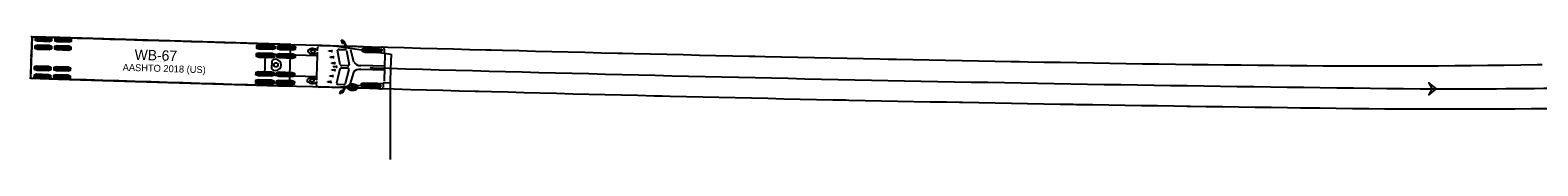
# Model space of a CAD drawing. Extents: x 973688 to 979179, y 703586 to 707602.
# Drawn here: x 976765.6 to 977073.4, y 704010.6 to 704035.6 of the extents above; entities that cross this region are included whole.
import ezdxf

# ---------------------------------------------------------------- set-up
doc = ezdxf.new("R2010")
doc.units = 0
doc.layers.add('SB Left', color=7, linetype='Continuous')
doc.layers.add('SB Right', color=7, linetype='Continuous')

msp = doc.modelspace()

# ---------------------------------------------------------------- linework, layer by layer
at = {"layer": 'SB Left'}
msp.add_line((976839.13, 704026.21), (976839.13, 704010.57), dxfattribs=at)
at = {"layer": 'SB Right'}
for p, q in [((976765.76, 704027.11), (976766.02, 704035.61)), ((976765.95, 704035.57), (976765.84, 704031.93)), ((976766.02, 704035.61), (976765.95, 704035.61)), ((976765.95, 704035.61), (976765.95, 704035.59)), ((976765.95, 704035.57), (976765.95, 704035.57)), ((976771.69, 704035.44), (976766.02, 704035.61)), ((976770.01, 704034.8), (976766.71, 704034.9)), ((976770.02, 704035.26), (976766.72, 704035.36)), ((976770.01, 704035.03), (976766.72, 704035.13)), ((976774.01, 704034.91), (976770.71, 704035.01)), ((976774.01, 704034.68), (976770.71, 704034.78)), ((976774.02, 704035.14), (976770.72, 704035.24)), ((976818.86, 704034.01), (976771.69, 704035.44)), ((976818.73, 704029.76), (976818.86, 704034.01)), ((976829.41, 704034.25), (976829.18, 704034.98)), ((976829.18, 704034.98), (976829.18, 704034.98)), ((976829.18, 704034.98), (976829.3, 704034.97)), ((976829.3, 704034.97), (976829.3, 704034.97)), ((976829.3, 704034.97), (976829.53, 704034.65)), ((976829.52, 704034.25), (976829.41, 704034.25)), ((976829.54, 704034.59), (976829.52, 704034.25)), ((976829.53, 704034.65), (976829.53, 704034.64)), ((976829.55, 704034.62), (976829.53, 704034.64)), ((976829.53, 704034.64), (976829.62, 704034.64)), ((976829.54, 704034.59), (976829.55, 704034.62)), ((976829.62, 704034.59), (976829.54, 704034.59)), ((976829.54, 704034.59), (976829.54, 704034.59)), ((976829.63, 704034.59), (976829.62, 704034.59)), ((976829.62, 704034.59), (976829.62, 704034.59)), ((976829.66, 704034.58), (976829.63, 704034.59)), ((976830.04, 704033.67), (976829.66, 704034.58)), ((976829.66, 704034.58), (976829.66, 704034.58)), ((976829.75, 704034.59), (976830.14, 704033.68)), ((976765.8, 704030.8), (976765.69, 704027.16)), ((976765.74, 704031.1), (976765.74, 704030.84)), ((976765.74, 704030.84), (976765.74, 704030.84)), ((976765.74, 704030.84), (976765.81, 704030.83)), ((976765.77, 704031.9), (976765.76, 704031.63)), ((976765.84, 704031.9), (976765.77, 704031.9)), ((976765.77, 704031.9), (976765.77, 704031.9)), ((976765.81, 704030.83), (976765.8, 704030.8)), ((976765.83, 704031.62), (976765.81, 704031.1)), ((976765.81, 704030.83), (976765.81, 704031.1)), ((976765.82, 704031.36), (976765.89, 704031.36)), ((976765.83, 704031.63), (976765.84, 704031.9)), ((976765.84, 704031.93), (976765.84, 704031.9)), ((976769.96, 704033.15), (976766.66, 704033.25)), ((976769.97, 704033.61), (976766.67, 704033.71)), ((976769.96, 704033.38), (976766.67, 704033.48)), ((976773.96, 704033.26), (976770.66, 704033.36)), ((976773.96, 704033.03), (976770.66, 704033.13)), ((976773.97, 704033.49), (976770.67, 704033.59)), ((976815.52, 704031.75), (976811.85, 704031.86)), ((976815.51, 704031.52), (976811.85, 704031.63)), ((976815.53, 704031.98), (976811.86, 704032.09)), ((976815.57, 704033.4), (976811.9, 704033.51)), ((976815.56, 704033.17), (976811.9, 704033.28)), ((976815.58, 704033.63), (976811.91, 704033.74)), ((976813.63, 704029.92), (976813.69, 704032.08)), ((976813.69, 704032.08), (976824.05, 704031.77)), ((976819.72, 704031.62), (976816.05, 704031.73)), ((976819.71, 704031.39), (976816.05, 704031.51)), ((976819.72, 704031.85), (976816.06, 704031.96)), ((976819.77, 704033.27), (976816.1, 704033.38)), ((976819.76, 704033.04), (976816.1, 704033.15)), ((976819.77, 704033.5), (976816.11, 704033.61)), ((976824.05, 704031.77), (976824.29, 704031.76)), ((976824.16, 704027.43), (976824.29, 704031.76)), ((976824.29, 704031.76), (976824.31, 704032.44)), ((976824.32, 704032.73), (976824.35, 704033.57)), ((976824.87, 704033.83), (976830.04, 704033.67)), ((976826.59, 704032.71), (976827.14, 704032.73)), ((976826.59, 704032.62), (976826.59, 704032.71)), ((976827.14, 704032.56), (976826.59, 704032.62)), ((976826.94, 704031.48), (976827.52, 704031.5)), ((976826.94, 704031.39), (976826.94, 704031.48)), ((976827.51, 704031.34), (976826.94, 704031.39)), ((976827.79, 704033.74), (976837.89, 704032.27)), ((976828.9, 704029.88), (976828.34, 704032.83)), ((976828.72, 704033.02), (976829.85, 704032.98)), ((976830.04, 704033.67), (976830.14, 704033.67)), ((976830.14, 704033.68), (976830.15, 704033.67)), ((976830.15, 704033.67), (976837.4, 704033.45)), ((976830.22, 704032.81), (976830.77, 704029.85)), ((976831.68, 704030.44), (976831.12, 704032.92)), ((976837.16, 704032.75), (976833.49, 704032.86)), ((976837.15, 704032.52), (976833.49, 704032.63)), ((976837.17, 704032.97), (976833.5, 704033.09)), ((976837.06, 704032.63), (976837.07, 704033.05)), ((976837.42, 704032.62), (976837.06, 704032.63)), ((976837.07, 704033.05), (976837.43, 704033.04)), ((976837.43, 704033.04), (976837.42, 704032.62)), ((976837.91, 704033.14), (976837.89, 704032.28)), ((976837.89, 704032.28), (976837.89, 704032.27)), ((976837.89, 704032.27), (976839.31, 704032.06)), ((976837.94, 704026.54), (976838.11, 704032.1)), ((976839.3, 704032), (976839.22, 704029.14)), ((976839.31, 704032.06), (976839.3, 704032)), ((976769.79, 704027.68), (976766.49, 704027.78)), ((976769.83, 704028.87), (976766.53, 704028.97)), ((976769.84, 704029.33), (976766.54, 704029.43)), ((976769.83, 704029.1), (976766.54, 704029.2)), ((976773.83, 704028.98), (976770.53, 704029.08)), ((976773.83, 704028.75), (976770.53, 704028.85)), ((976773.84, 704029.21), (976770.54, 704029.31)), ((976815.4, 704027.74), (976811.73, 704027.85)), ((976815.4, 704027.97), (976811.74, 704028.08)), ((976815.41, 704028.2), (976811.75, 704028.31)), ((976813.56, 704027.75), (976813.63, 704029.92)), ((976823.92, 704027.44), (976813.56, 704027.75)), ((976814.94, 704030.68), (976814.9, 704029.06)), ((976819.6, 704027.61), (976815.93, 704027.72)), ((976819.61, 704028.07), (976815.94, 704028.18)), ((976819.6, 704027.84), (976815.94, 704027.95)), ((976818.6, 704025.51), (976818.73, 704029.76)), ((976827.19, 704028.75), (976827.2, 704028.84)), ((976827.74, 704028.7), (976827.19, 704028.75)), ((976827.2, 704028.84), (976827.75, 704028.86)), ((976827.24, 704030.25), (976827.79, 704030.28)), ((976827.24, 704030.16), (976827.24, 704030.25)), ((976827.78, 704030.11), (976827.24, 704030.16)), ((976827.52, 704029.45), (976827.53, 704029.54)), ((976828.07, 704029.39), (976827.52, 704029.45)), ((976827.53, 704029.54), (976828.08, 704029.56)), ((976828.87, 704029.03), (976828.14, 704026.11)), ((976830.38, 704029.15), (976829.25, 704029.18)), ((976830.39, 704029.67), (976829.26, 704029.7)), ((976830.01, 704026.02), (976830.74, 704028.94)), ((976831.62, 704028.3), (976830.91, 704025.84)), ((976838, 704028.76), (976833.11, 704028.91)), ((976838.03, 704029.59), (976833.14, 704029.74)), ((976839.22, 704029.14), (976839.13, 704026.28)), ((976765.69, 704027.16), (976765.69, 704027.16)), ((976765.69, 704027.14), (976765.69, 704027.12)), ((976765.69, 704027.12), (976765.76, 704027.12)), ((976765.76, 704027.12), (976771.43, 704026.94)), ((976769.78, 704027.22), (976766.48, 704027.32)), ((976769.78, 704027.45), (976766.49, 704027.55)), ((976773.78, 704027.33), (976770.48, 704027.43)), ((976773.78, 704027.1), (976770.48, 704027.2)), ((976773.79, 704027.56), (976770.49, 704027.66)), ((976771.43, 704026.94), (976818.6, 704025.51)), ((976815.35, 704026.09), (976811.68, 704026.2)), ((976815.35, 704026.32), (976811.69, 704026.43)), ((976815.36, 704026.55), (976811.7, 704026.66)), ((976819.55, 704025.96), (976815.88, 704026.07)), ((976819.56, 704026.42), (976815.89, 704026.53)), ((976819.55, 704026.19), (976815.89, 704026.3)), ((976824.16, 704027.43), (976823.92, 704027.44)), ((976824.1, 704025.62), (976824.13, 704026.46)), ((976824.14, 704026.74), (976824.16, 704027.43)), ((976829.78, 704025.17), (976824.61, 704025.33)), ((976826.4, 704026.43), (976826.95, 704026.45)), ((976826.4, 704026.34), (976826.4, 704026.43)), ((976826.95, 704026.28), (976826.4, 704026.34)), ((976826.82, 704027.55), (976826.83, 704027.64)), ((976827.37, 704027.49), (976826.82, 704027.55)), ((976826.83, 704027.64), (976827.38, 704027.66)), ((976827.53, 704025.24), (976830.33, 704025.48)), ((976828.5, 704025.9), (976829.63, 704025.87)), ((976828.84, 704023.92), (976829.12, 704024.63)), ((976829.12, 704024.63), (976829.22, 704024.63)), ((976829.35, 704024.29), (976829.78, 704025.17)), ((976829.88, 704025.16), (976829.44, 704024.27)), ((976829.78, 704025.17), (976829.88, 704025.17)), ((976829.89, 704025.17), (976829.88, 704025.16)), ((976830.32, 704025.16), (976829.89, 704025.17)), ((976832.29, 704025.64), (976837.7, 704026.09)), ((976837.14, 704024.95), (976832.5, 704025.09)), ((976836.94, 704025.44), (976833.27, 704025.55)), ((976836.94, 704025.66), (976833.28, 704025.78)), ((976836.95, 704025.89), (976833.29, 704026.01)), ((976836.85, 704025.78), (976836.84, 704025.37)), ((976836.84, 704025.37), (976837.2, 704025.36)), ((976837.21, 704025.77), (976836.85, 704025.78)), ((976837.2, 704025.36), (976837.21, 704025.77)), ((976837.7, 704026.09), (976837.67, 704025.23)), ((976839.13, 704026.21), (976837.7, 704026.09)), ((976837.7, 704026.09), (976837.7, 704026.09)), ((976839.13, 704026.28), (976839.13, 704026.21)), ((976828.96, 704023.92), (976828.84, 704023.92)), ((976828.84, 704023.92), (976828.84, 704023.92)), ((976829.21, 704024.23), (976828.96, 704023.92)), ((976828.96, 704023.92), (976828.96, 704023.92)), ((976829.23, 704024.25), (976829.21, 704024.23)), ((976829.3, 704024.23), (976829.21, 704024.23)), ((976829.21, 704024.23), (976829.21, 704024.23)), ((976829.22, 704024.63), (976829.23, 704024.28)), ((976829.23, 704024.28), (976829.23, 704024.25)), ((976829.23, 704024.28), (976829.23, 704024.28)), ((976829.23, 704024.28), (976829.31, 704024.28)), ((976829.31, 704024.28), (976829.35, 704024.29)), ((976829.31, 704024.28), (976829.31, 704024.28)), ((976829.31, 704024.28), (976829.31, 704024.28)), ((976829.35, 704024.29), (976829.35, 704024.29))]:
    msp.add_line(p, q, dxfattribs=at)
for points in [[(976894.63, 704023.45), (976892.98, 704023.49), (976889.66, 704023.57), (976886.34, 704023.65), (976883.03, 704023.74), (976879.71, 704023.82), (976876.4, 704023.9), (976873.08, 704023.99), (976869.77, 704024.07), (976866.45, 704024.16), (976863.13, 704024.25), (976859.82, 704024.34), (976857.17, 704024.41), (976856.5, 704024.42), (976853.19, 704024.51), (976849.87, 704024.61), (976846.56, 704024.7), (976843.24, 704024.79), (976839.93, 704024.89), (976836.61, 704024.98), (976833.29, 704025.08), (976829.98, 704025.17), (976826.66, 704025.27), (976823.35, 704025.37), (976820.03, 704025.47), (976816.72, 704025.57), (976813.4, 704025.67), (976810.09, 704025.77), (976806.77, 704025.87), (976803.47, 704025.97), (976800.18, 704026.07), (976796.9, 704026.17), (976793.62, 704026.27), (976790.34, 704026.37), (976787.05, 704026.47), (976783.74, 704026.57), (976780.44, 704026.67), (976777.13, 704026.77), (976773.82, 704026.87), (976771.17, 704026.95), (976770.07, 704026.98), (976768.96, 704027.02), (976767.86, 704027.05), (976766.75, 704027.08), (976765.88, 704027.11), (976765.74, 704027.12), (976766.08, 704035.61)], [(976766.08, 704035.61), (976767.2, 704035.58), (976768.31, 704035.54), (976769.43, 704035.51), (976770.54, 704035.47), (976771.88, 704035.43), (976775.22, 704035.33), (976778.57, 704035.23), (976781.91, 704035.13), (976785.24, 704035.03), (976788.58, 704034.93), (976791.9, 704034.83), (976795.21, 704034.73), (976798.52, 704034.63), (976801.83, 704034.53), (976803.5, 704034.48), (976805.16, 704034.43), (976808.51, 704034.34), (976811.85, 704034.24), (976815.2, 704034.14), (976818.55, 704034.04), (976821.9, 704033.95), (976825.25, 704033.85), (976828.6, 704033.76), (976831.94, 704033.66), (976832.28, 704033.65), (976835.29, 704033.57), (976838.64, 704033.48), (976841.99, 704033.38), (976845.34, 704033.29), (976848.69, 704033.2), (976852.04, 704033.11), (976855.39, 704033.02), (976858.73, 704032.93), (976859.74, 704032.91), (976862.08, 704032.85), (976865.43, 704032.76), (976868.78, 704032.67), (976872.13, 704032.59), (976875.48, 704032.51), (976878.83, 704032.42), (976882.18, 704032.34), (976885.53, 704032.26), (976886.53, 704032.23), (976888.88, 704032.18), (976892.23, 704032.1), (976895.57, 704032.02), (976898.92, 704031.94), (976902.27, 704031.86), (976905.62, 704031.78), (976908.97, 704031.71), (976912.32, 704031.63), (976913.66, 704031.6), (976915.67, 704031.56), (976919.02, 704031.49), (976922.37, 704031.41), (976925.72, 704031.34), (976929.07, 704031.27), (976932.42, 704031.2), (976935.77, 704031.13), (976939.11, 704031.07), (976940.79, 704031.03), (976942.46, 704031), (976945.81, 704030.93), (976949.16, 704030.87), (976952.51, 704030.8), (976955.86, 704030.74), (976959.21, 704030.68), (976962.56, 704030.62), (976965.91, 704030.55), (976967.59, 704030.53), (976969.26, 704030.5), (976972.61, 704030.44), (976975.96, 704030.38), (976979.31, 704030.32), (976982.66, 704030.27), (976986.01, 704030.21), (976989.36, 704030.16), (976992.71, 704030.1), (976994.38, 704030.08), (976996.06, 704030.05), (976999.41, 704030), (977002.76, 704029.95), (977006.11, 704029.91), (977009.46, 704029.87), (977011.14, 704029.85), (977012.81, 704029.83), (977016.16, 704029.79), (977019.52, 704029.76), (977022.87, 704029.73), (977025.89, 704029.71), (977026.23, 704029.71), (977029.58, 704029.69), (977032.94, 704029.67), (977036.3, 704029.66), (977039.65, 704029.65), (977043.01, 704029.65), (977046.37, 704029.66), (977049.73, 704029.67), (977053.09, 704029.68), (977056.45, 704029.7), (977059.81, 704029.73), (977063.17, 704029.77), (977064.18, 704029.78), (977066.53, 704029.81), (977069.89, 704029.87), (977073.25, 704029.94), (977074.26, 704029.96)], [(976835.22, 704029.26), (976835.55, 704029.25)], [(977052.74, 704024.95), (977051.17, 704026.19), (977051.74, 704024.96), (977051.14, 704023.75), (977052.74, 704024.95)], [(977052.74, 704024.95), (977053.08, 704024.95), (977053.41, 704024.95)], [(977075.32, 704020.89), (977072.01, 704020.86), (977068.7, 704020.83), (977068.36, 704020.82), (977065.38, 704020.8), (977062.07, 704020.79), (977058.76, 704020.78), (977058.09, 704020.78), (977055.44, 704020.78), (977052.13, 704020.78), (977048.81, 704020.79), (977047.82, 704020.8), (977045.5, 704020.81), (977042.18, 704020.83), (977038.87, 704020.87), (977035.56, 704020.9), (977032.24, 704020.95), (977028.93, 704020.99), (977025.62, 704021.03), (977024.95, 704021.04), (977022.3, 704021.07), (977018.99, 704021.12), (977015.67, 704021.16), (977012.35, 704021.21), (977009.04, 704021.26), (977005.72, 704021.31), (977002.41, 704021.36), (977001.74, 704021.37), (976999.09, 704021.41), (976995.78, 704021.46), (976992.46, 704021.51), (976989.14, 704021.56), (976985.83, 704021.62), (976982.51, 704021.67), (976979.19, 704021.73), (976978.53, 704021.74), (976975.88, 704021.78), (976972.56, 704021.84), (976969.25, 704021.9), (976965.93, 704021.96), (976962.61, 704022.02), (976959.3, 704022.08), (976955.98, 704022.14), (976955.32, 704022.15), (976952.66, 704022.21), (976949.35, 704022.27), (976946.03, 704022.33), (976942.72, 704022.4), (976939.4, 704022.47), (976936.08, 704022.53), (976932.77, 704022.6), (976932.1, 704022.62), (976929.45, 704022.67), (976926.14, 704022.74), (976922.82, 704022.81), (976919.5, 704022.88), (976916.19, 704022.96), (976912.87, 704023.03), (976909.56, 704023.11), (976906.24, 704023.18), (976902.92, 704023.26), (976899.61, 704023.33), (976896.29, 704023.41), (976894.63, 704023.45)]]:
    msp.add_lwpolyline(points, dxfattribs=at)
for points in [[(976769.97, 704033.67), (976769.96, 704033.1), (976769.49, 704032.94), (976767.11, 704033.01), (976766.66, 704033.2), (976766.67, 704033.77), (976767.14, 704033.93), (976769.52, 704033.85)], [(976770.02, 704035.32), (976770.01, 704034.75), (976769.54, 704034.59), (976767.16, 704034.66), (976766.71, 704034.85), (976766.72, 704035.42), (976767.19, 704035.58), (976769.57, 704035.5)], [(976774.02, 704035.2), (976774, 704034.62), (976773.54, 704034.47), (976771.16, 704034.54), (976770.71, 704034.72), (976770.72, 704035.3), (976771.19, 704035.45), (976773.56, 704035.38)], [(976815.58, 704033.69), (976815.56, 704033.11), (976815.04, 704032.96), (976812.4, 704033.04), (976811.9, 704033.22), (976811.91, 704033.8), (976812.43, 704033.95), (976815.07, 704033.87)], [(976773.97, 704033.55), (976773.95, 704032.97), (976773.49, 704032.82), (976771.11, 704032.89), (976770.66, 704033.07), (976770.67, 704033.65), (976771.14, 704033.8), (976773.51, 704033.73)], [(976815.53, 704032.04), (976815.51, 704031.46), (976814.99, 704031.31), (976812.35, 704031.39), (976811.85, 704031.58), (976811.86, 704032.15), (976812.38, 704032.3), (976815.02, 704032.22)], [(976819.73, 704031.91), (976819.71, 704031.34), (976819.19, 704031.18), (976816.55, 704031.26), (976816.04, 704031.45), (976816.06, 704032.02), (976816.58, 704032.18), (976819.22, 704032.1)], [(976819.78, 704033.56), (976819.76, 704032.99), (976819.24, 704032.83), (976816.6, 704032.91), (976816.09, 704033.1), (976816.11, 704033.67), (976816.63, 704033.83), (976819.27, 704033.75)], [(976837.17, 704033.03), (976837.15, 704032.46), (976836.63, 704032.3), (976833.99, 704032.38), (976833.49, 704032.57), (976833.5, 704033.14), (976834.02, 704033.3), (976836.66, 704033.22)], [(976769.79, 704027.74), (976769.78, 704027.17), (976769.31, 704027.01), (976766.93, 704027.08), (976766.48, 704027.27), (976766.49, 704027.84), (976766.96, 704028), (976769.34, 704027.92)], [(976769.84, 704029.39), (976769.83, 704028.81), (976769.36, 704028.66), (976766.98, 704028.73), (976766.53, 704028.91), (976766.54, 704029.49), (976767.01, 704029.64), (976769.39, 704029.57)], [(976773.79, 704027.62), (976773.77, 704027.04), (976773.31, 704026.89), (976770.93, 704026.96), (976770.48, 704027.14), (976770.49, 704027.72), (976770.96, 704027.87), (976773.33, 704027.8)], [(976773.84, 704029.27), (976773.82, 704028.69), (976773.36, 704028.54), (976770.98, 704028.61), (976770.53, 704028.79), (976770.54, 704029.37), (976771.01, 704029.52), (976773.38, 704029.45)], [(976815.41, 704028.25), (976815.4, 704027.68), (976814.88, 704027.53), (976812.24, 704027.61), (976811.73, 704027.79), (976811.75, 704028.37), (976812.27, 704028.52), (976814.91, 704028.44)], [(976819.61, 704028.13), (976819.59, 704027.56), (976819.08, 704027.4), (976816.44, 704027.48), (976815.93, 704027.67), (976815.95, 704028.24), (976816.46, 704028.4), (976819.1, 704028.32)], [(976815.36, 704026.61), (976815.35, 704026.03), (976814.83, 704025.88), (976812.19, 704025.96), (976811.68, 704026.14), (976811.7, 704026.72), (976812.22, 704026.87), (976814.86, 704026.79)], [(976819.56, 704026.48), (976819.54, 704025.91), (976819.03, 704025.75), (976816.39, 704025.83), (976815.88, 704026.02), (976815.9, 704026.59), (976816.41, 704026.75), (976819.05, 704026.67)], [(976836.95, 704025.95), (976836.94, 704025.38), (976836.42, 704025.22), (976833.78, 704025.3), (976833.27, 704025.49), (976833.29, 704026.06), (976833.81, 704026.22), (976836.45, 704026.14)], [(977052.74, 704024.95), (977051.17, 704026.19), (977051.74, 704024.96), (977051.14, 704023.75)]]:
    msp.add_lwpolyline(points, close=True, dxfattribs=at)
for centre, radius in [((976765.92, 704035.58), 0.0266), ((976815.8, 704029.85), 0.424), ((976835.22, 704029.26), 0.0417), ((976835.55, 704029.25), 0.0417), ((976835.55, 704029.25), 0.0417), ((976765.66, 704027.15), 0.0266), ((977052.74, 704024.95), 0.0417), ((977052.74, 704024.95), 0.0417), ((977053.41, 704024.95), 0.0417), ((977053.41, 704024.95), 0.0417)]:
    msp.add_circle(centre, radius, dxfattribs=at)
for centre, radius, start, end in [((976765.92, 704035.58), 0.0363, 17.3407, 338.5021), ((976829.68, 704034.55), 0.108, 79.1044, 125.2869), ((976829.7, 704034.61), 0.0522, 344.5261, 89.3807), ((976765.78, 704031.1), 0.0352, 359.2376, 178.238), ((976765.78, 704031.1), 0.0354, 182.5548, 354.7403), ((976765.79, 704031.63), 0.0353, 1.5994, 179.9491), ((976765.79, 704031.63), 0.0352, 178.2885, 357.2889), ((976815.73, 704029.85), 1.14, 223.2633, 133.2633), ((976822.68, 704032.64), 0.346, 121.656, 218.669), ((976823.23, 704033.21), 1.14, 224.0272, 265.548), ((976823.28, 704031.75), 1.42, 86.1914, 123.2593), ((976823.05, 704032.62), 0.172, 118.5649, 205.7155), ((976823.2, 704032.74), 0.362, 212.5598, 261.6008), ((976823.31, 704032.21), 0.664, 83.1671, 121.3888), ((976823.35, 704033.09), 0.732, 253.4371, 299.6715), ((976823.38, 704033.79), 1.73, 262.0899, 286.8884), ((976823.42, 704032.03), 1.14, 37.8932, 92.6845), ((976823.39, 704032.35), 0.522, 43.2686, 90.4328), ((976823.64, 704032.6), 0.169, 296.6976, 36.8163), ((976823.7, 704032.85), 0.729, 284.0718, 326.5857), ((976824.85, 704033.21), 0.619, 88.2612, 144.103), ((976827.19, 704032.58), 0.157, 21.8092, 108.9189), ((976827.19, 704032.74), 0.184, 255.2164, 327.1085), ((976827.54, 704031.36), 0.157, 21.8092, 108.9189), ((976827.53, 704031.51), 0.184, 255.2164, 327.1085), ((976828.65, 704032.69), 0.332, 77.1847, 155.6067), ((976829.89, 704032.6), 0.387, 32.5961, 95.8281), ((976837.46, 704032.96), 0.486, 20.7262, 96.6773), ((976827.8, 704028.84), 0.157, 247.6076, 334.7173), ((976827.78, 704028.68), 0.184, 29.4181, 101.3101), ((976827.83, 704030.29), 0.184, 255.2164, 327.1085), ((976827.84, 704030.13), 0.157, 21.8092, 108.9189), ((976828.13, 704029.54), 0.157, 247.6076, 334.7173), ((976828.13, 704029.41), 0.157, 21.8092, 108.9189), ((976829.19, 704028.8), 0.387, 80.7009, 143.928), ((976829.23, 704030.09), 0.387, 212.5986, 275.8256), ((976830.46, 704028.86), 0.296, 14.982, 105.2797), ((976830.49, 704029.95), 0.296, 251.2468, 341.5445), ((976832.85, 704027.41), 1.52, 79.8433, 144.2707), ((976832.96, 704031.25), 1.52, 212.2558, 276.6832), ((977185.14, 716202.27), 12178.04, 268.355009, 269.377078), ((976763.67, 704027.2), 2.02, 358.2633, 358.947), ((976822.5, 704026.65), 0.346, 137.8575, 234.8706), ((976823.01, 704026.04), 1.14, 90.9786, 132.4993), ((976823.15, 704027.5), 1.42, 233.2673, 270.3351), ((976822.87, 704026.64), 0.172, 150.8111, 237.9617), ((976823.01, 704026.51), 0.362, 94.9257, 143.9667), ((976823.15, 704027.04), 0.664, 235.1377, 273.3594), ((976823.14, 704026.16), 0.732, 56.855, 103.0894), ((976823.12, 704025.45), 1.73, 69.6381, 94.4366), ((976823.28, 704027.21), 1.14, 263.842, 318.6333), ((976823.23, 704026.9), 0.522, 266.0938, 313.2579), ((976823.46, 704026.63), 0.169, 319.7102, 59.8289), ((976823.51, 704026.38), 0.729, 29.9408, 72.4548), ((976824.63, 704025.95), 0.619, 212.4236, 268.2653), ((976826.99, 704026.27), 0.184, 29.4181, 101.3101), ((976827.01, 704026.43), 0.157, 247.6076, 334.7173), ((976827.43, 704027.63), 0.157, 247.6076, 334.7173), ((976827.41, 704027.48), 0.184, 29.4181, 101.3101), ((976828.45, 704026.23), 0.332, 200.9199, 279.3419), ((976829.7, 704026.25), 0.387, 260.6984, 323.9304), ((976830.63, 704025.31), 0.347, 150.5905, 205.4011), ((976831.44, 704026.2), 1.53, 222.756, 313.765), ((976831.21, 704024.76), 1.14, 86.9678, 140.7704), ((976831.14, 704025.18), 0.44, 100.0575, 163.8704), ((976831.04, 704025.33), 0.317, 184.1135, 245.7059), ((976831.4, 704025.94), 1.03, 241.0869, 269.4734), ((976831.3, 704025.21), 0.263, 87.1982, 161.1001), ((976831.22, 704025.31), 0.17, 185.9323, 239.9967), ((976831.38, 704024.47), 1.19, 69.3945, 105.2838), ((976831.42, 704025.68), 0.589, 241.0188, 284.0015), ((976831.39, 704024.19), 1.7, 58.1839, 94.092), ((976831.39, 704024.9), 0.575, 61.3384, 97.9087), ((976831.52, 704025.53), 0.634, 258.8471, 334.8488), ((976831.54, 704025.33), 0.223, 275.4982, 345.1007), ((976831.6, 704025.26), 0.158, 3.2345, 64.7472), ((976831.73, 704025.22), 0.366, 6.3156, 78.7966), ((976832.1, 704025.26), 0.425, 336.3262, 62.8626), ((976837.23, 704025.43), 0.486, 259.8492, 335.8003), ((977054.27, 705676.46), 1651.51, 269.97034, 272.10923), ((976829.37, 704024.31), 0.108, 231.2396, 277.4221), ((976829.38, 704024.26), 0.0522, 267.1459, 12.0005)]:
    msp.add_arc(centre, radius, start, end, dxfattribs=at)
for centre, major_axis, start_param, end_param in [((976829.68, 704034.62), (0.0782, -0.0024), 2.615166, 3.884468), ((976829.68, 704034.62), (-0.0782, 0.0024), 1.301202, 2.571945), ((976829.37, 704024.25), (0.0782, -0.0024), 2.398717, 3.668019), ((976829.37, 704024.25), (0.0782, -0.0024), 0.569648, 1.840391)]:
    msp.add_ellipse(centre, major_axis=major_axis, ratio=0.544872, start_param=start_param, end_param=end_param, dxfattribs=at)

# ---------------------------------------------------------------- texts
for s, height, p in [('WB-67', 2.125, (976786.93, 704030.89)), ('AASHTO 2018 (US)', 1.4167, (976784.51, 704028.66)), ('(c) 2022 Transoft Solutions, Inc. All rights reserved.', 0.085, (976790.5, 704030.57))]:
    msp.add_text(s, height=height, rotation=358.2633, dxfattribs=at).set_placement(p)

doc.saveas('drawing.dxf')
